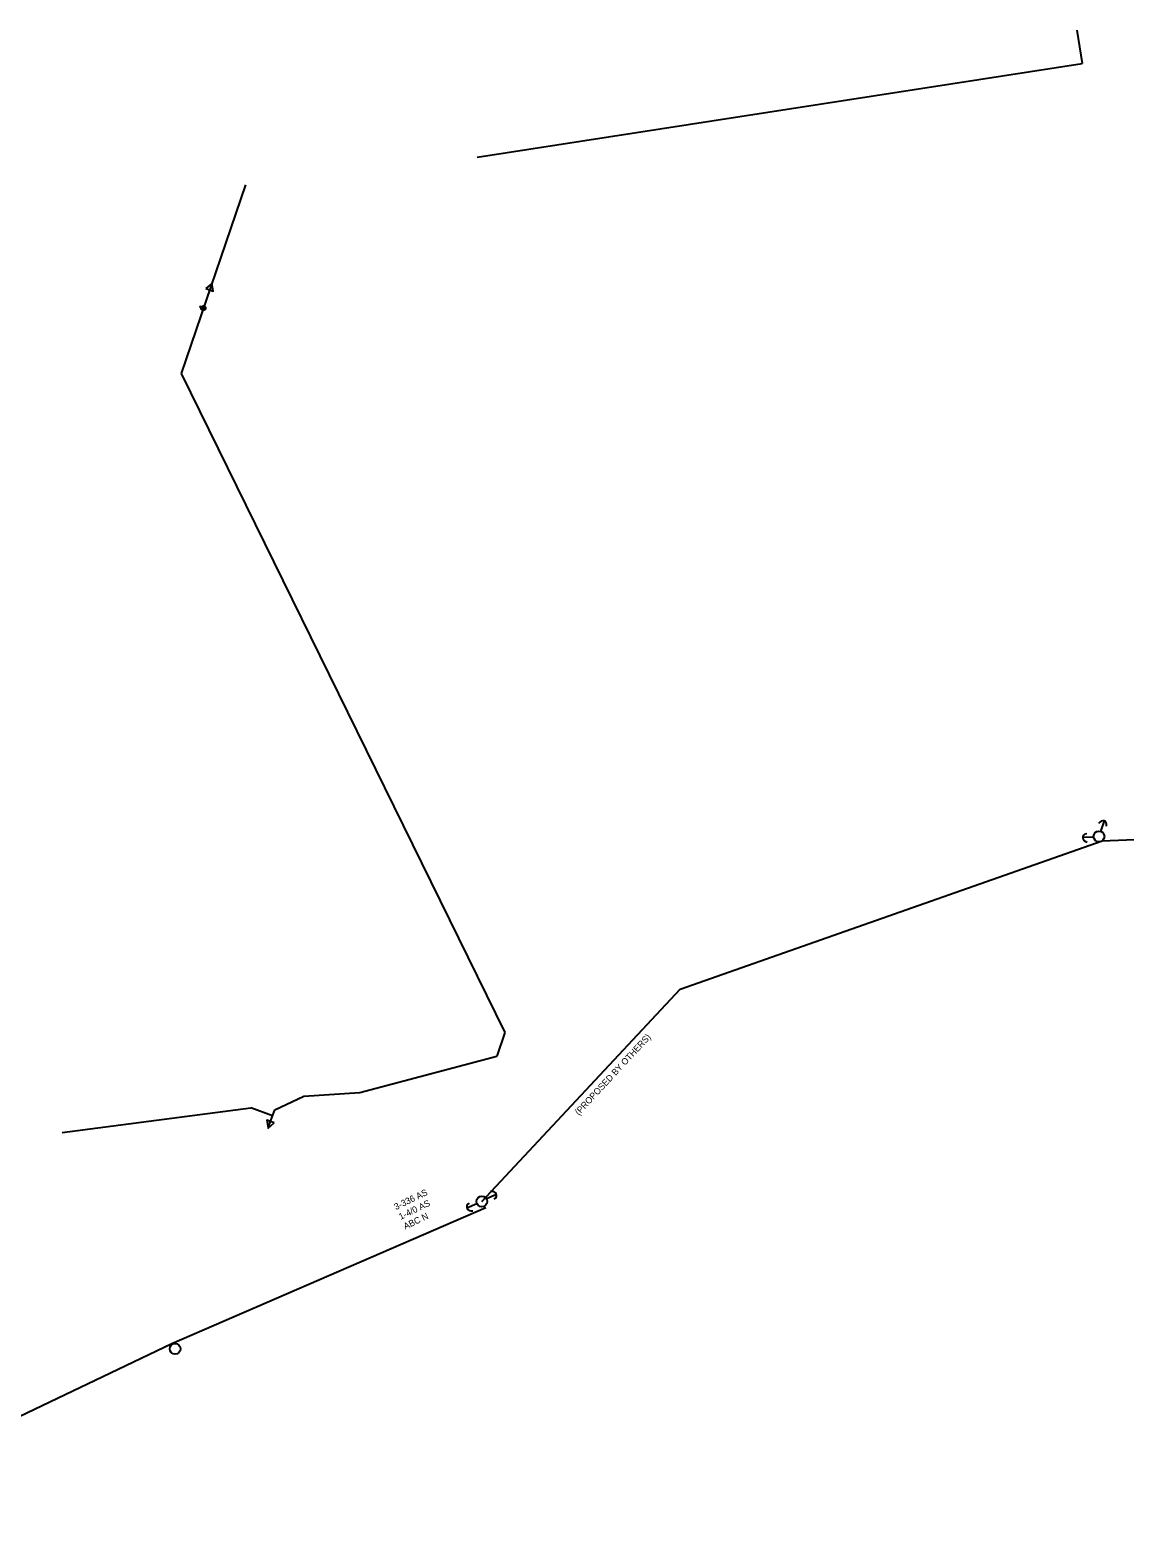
# Model space of a CAD drawing. Extents: x 1825330 to 1832613, y 710925 to 712586.
# Drawn here: x 1826006 to 1826516, y 711347 to 712050 of the extents above; entities that cross this region are included whole.
import ezdxf

# ---------------------------------------------------------------- set-up
doc = ezdxf.new("R2010")
doc.units = 0
for name, color, linetype in [('1', 7, 'Continuous'), ('COC_MIS_UBOX', 7, 'Continuous'), ('COC_UCMS_MH', 7, 'Continuous'), ('COC_UELC_GUY', 7, 'Continuous'), ('COC_UWAT_HYD', 7, 'Continuous'), ('CT-DEMO-XOUT-D', 7, 'Continuous'), ('P-TEXT', 7, 'Continuous'), ('SH_Text', 7, 'Continuous')]:
    doc.layers.add(name, color=color, linetype=linetype)

# ---------------------------------------------------------------- blocks, each defined once
blk = doc.blocks.new('A$C5CB60854')
blk.add_line((0.059, 0.104), (0.02, 0.003))
blk.add_ellipse((0.048, 0.057), major_axis=(-0.0296, -0.0526), ratio=0.727425, start_param=5.152157, end_param=7.659178)
blk = doc.blocks.new('A$C36531AE1')
blk.add_circle((0.053, 0.053), 0.0529)

msp = doc.modelspace()

# ---------------------------------------------------------------- linework, layer by layer
at = {"layer": '1'}
for p in [(1826493.24, 712049.74), (1826213.88, 711990.49)]:
    msp.add_line(p, (1826495.65, 712034.13), dxfattribs=at)
at = {"layer": 'COC_UELC_GUY'}
for p, q in [((1826105.85, 711977.72), (1826075.88, 711889.84)), ((1826075.88, 711889.84), (1826226.76, 711582.77)), ((1826226.76, 711582.77), (1826223, 711571.74)), ((1826159.23, 711554.76), (1826223, 711571.74)), ((1826119.51, 711546.73), (1826133.13, 711553.08)), ((1826133.13, 711553.08), (1826159.23, 711554.76)), ((1826020.51, 711536.18), (1826108.39, 711547.58)), ((1826118.48, 711543.91), (1826108.39, 711547.58)), ((1826116.77, 711539.21), (1826119.51, 711546.73))]:
    msp.add_line(p, q, dxfattribs=at)
for points in [[(1826087.39, 711929.31), (1826090.82, 711928.06), (1826090.19, 711931.66)], [(1826119.21, 711540.57), (1826115.77, 711541.82), (1826116.41, 711538.22)]]:
    msp.add_lwpolyline(points, close=True, dxfattribs=at)
at = {"layer": 'COC_UWAT_HYD'}
for p, q in [((1826505.09, 711672), (1826671.54, 711678.8)), ((1826308.47, 711602.91), (1826505.09, 711672)), ((1826215.95, 711504), (1826308.47, 711602.91))]:
    msp.add_line(p, q, dxfattribs=at)
at = {"layer": 'P-TEXT'}
for p, q in [((1826085.27, 711920.63), (1826084.4, 711921)), ((1826085.02, 711921.26), (1826084.65, 711920.38))]:
    msp.add_line(p, q, dxfattribs=at)
msp.add_lwpolyline([(1826085.5, 711920.01), (1826086.78, 711919.72), (1826085.68, 711920.45), (1826086.97, 711920.16), (1826085.87, 711920.89)], dxfattribs=at)
msp.add_circle((1826086.24, 711920.22), 1.05, dxfattribs=at)
at = {"layer": 'SH_Text'}
for p, q in [((1826217.81, 711501.08), (1826071.63, 711437.62)), ((1826071.63, 711437.62), (1825882.06, 711347.29))]:
    msp.add_line(p, q, dxfattribs=at)

# ---------------------------------------------------------------- block references
for name, p, xscale, yscale, rotation in [('A$C5CB60854', (1826507.06, 711681.47), 47.24400000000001, 47.244, -177.79622780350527), ('A$C5CB60854', (1826495.45, 711674.41), 47.244, 47.244000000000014, -67.2570857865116), ('A$C36531AE1', (1826501.05, 711671.57), 47.244000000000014, 47.24399999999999, 0.002586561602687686)]:
    msp.add_blockref(name, p, dxfattribs=dict(xscale=xscale, yscale=yscale, rotation=rotation))
at = {"layer": 'CT-DEMO-XOUT-D'}
for name, p, xscale, yscale, rotation in [('A$C5CB60854', (1826208.26, 711501.48), 47.244, 47.24400000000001, -44.997413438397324), ('A$C36531AE1', (1826213.51, 711501.52), 47.244000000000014, 47.24399999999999, 0.002586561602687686), ('A$C5CB60854', (1826223.6, 711506.84), 47.244, 47.24400000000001, 135.0025865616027), ('A$C36531AE1', (1826070.6, 711432.83), 47.244000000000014, 47.24399999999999, 0.002586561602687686)]:
    msp.add_blockref(name, p, dxfattribs=dict(at, xscale=xscale, yscale=yscale, rotation=rotation))

# ---------------------------------------------------------------- texts
at = {"layer": 'COC_MIS_UBOX'}
for s, p in [('3-336 AS', (1826176, 711499.95)), ('1-4/0 AS', (1826178.2, 711495.41)), ('ABC N', (1826180.4, 711490.86))]:
    msp.add_text(s, height=3, rotation=25.83149, dxfattribs=at).set_placement(p)
at = {"layer": 'COC_UCMS_MH'}
msp.add_text('(PROPOSED BY OTHERS)', height=3, rotation=47.20111, dxfattribs=at).set_placement((1826261.23, 711543.93))

doc.saveas('drawing.dxf')
